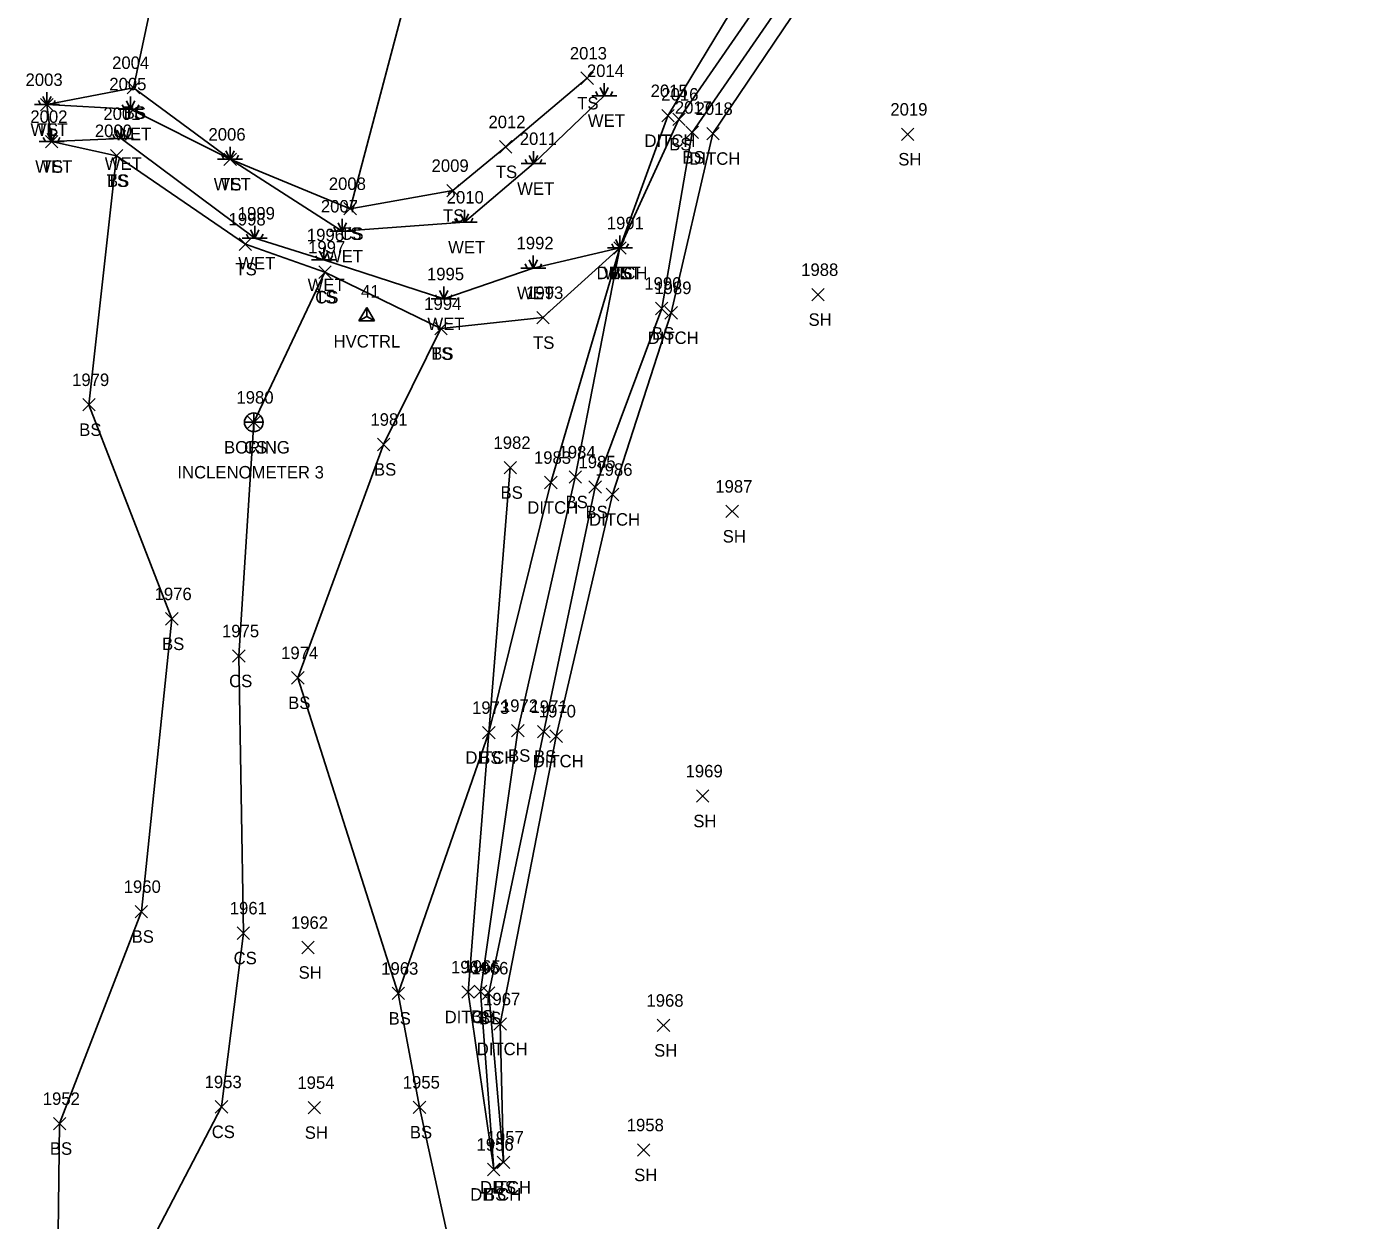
# Model space of a CAD drawing. Extents: x 1551995 to 1555700, y 777276 to 783130.
# Drawn here: x 1555046.7 to 1555258.3, y 777809.8 to 778001.3 of the extents above; entities that cross this region are included whole.
import ezdxf

# ---------------------------------------------------------------- set-up
doc = ezdxf.new("R2010")
doc.units = 0
for name, color, linetype in [('C_A', 7, 'Continuous'), ('C_I', 7, 'Continuous'), ('CPSM', 7, 'Continuous'), ('D_A', 7, 'Continuous'), ('D_I', 7, 'Continuous'), ('D_TIC', 7, 'Continuous'), ('DD', 7, 'Continuous'), ('G_A', 7, 'Continuous'), ('G_C', 7, 'Continuous'), ('G_I', 7, 'Continuous'), ('GA_P', 7, 'Continuous'), ('L_A', 7, 'Continuous'), ('L_I', 7, 'Continuous'), ('L_TIC', 7, 'Continuous'), ('LELB', 7, 'Continuous'), ('LWET', 7, 'Continuous')]:
    doc.layers.add(name, color=color, linetype=linetype)

msp = doc.modelspace()

# ---------------------------------------------------------------- linework, layer by layer
at = {"layer": 'CPSM'}
for p, q in [((1555100.02, 777954.05), (1555101.27, 777956.21)), ((1555102.52, 777954.05), (1555101.27, 777956.21)), ((1555101.27, 777954.77), (1555101.27, 777956.21)), ((1555100.02, 777954.05), (1555101.27, 777954.77)), ((1555100.02, 777954.05), (1555102.52, 777954.05)), ((1555101.27, 777954.77), (1555101.27, 777954.77)), ((1555101.27, 777954.77), (1555102.52, 777954.05))]:
    msp.add_line(p, q, dxfattribs=at)
at = {"layer": 'D_TIC'}
for points in [[(1555148.54, 777985.93), (1555150.54, 777987.93)], [(1555150.54, 777985.93), (1555148.54, 777987.93)], [(1555155.75, 777983.07), (1555157.75, 777985.07)], [(1555157.75, 777983.07), (1555155.75, 777985.07)], [(1555140.86, 777964.73), (1555142.86, 777966.73)], [(1555142.86, 777964.73), (1555140.86, 777966.73)], [(1555149.07, 777954.34), (1555151.07, 777956.34)], [(1555151.07, 777954.34), (1555149.07, 777956.34)], [(1555129.77, 777927.13), (1555131.77, 777929.13)], [(1555131.77, 777927.13), (1555129.77, 777929.13)], [(1555139.67, 777925.21), (1555141.67, 777927.21)], [(1555141.67, 777925.21), (1555139.67, 777927.21)], [(1555119.85, 777887.04), (1555121.85, 777889.04)], [(1555121.85, 777887.04), (1555119.85, 777889.04)], [(1555130.63, 777886.47), (1555132.63, 777888.47)], [(1555132.63, 777886.47), (1555130.63, 777888.47)], [(1555116.52, 777845.44), (1555118.52, 777847.44)], [(1555118.52, 777845.44), (1555116.52, 777847.44)], [(1555121.67, 777840.32), (1555123.67, 777842.32)], [(1555123.67, 777840.32), (1555121.67, 777842.32)], [(1555122.19, 777818.14), (1555124.19, 777820.14)], [(1555124.19, 777818.14), (1555122.19, 777820.14)], [(1555120.62, 777817), (1555122.62, 777819)], [(1555122.62, 777817), (1555120.62, 777819)], [(1555120.62, 777817), (1555122.62, 777819)], [(1555122.62, 777817), (1555120.62, 777819)]]:
    msp.add_lwpolyline(points, dxfattribs=at)
at = {"layer": 'DD'}
for points in [[(1555121.62, 777818), (1555123.19, 777819.14), (1555122.67, 777841.32), (1555131.63, 777887.47), (1555140.67, 777926.21), (1555150.07, 777955.34), (1555156.75, 777984.07), (1555186.15, 778027.75), (1555203.27, 778046.42), (1555232.38, 778067.51)], [(1555121.62, 777818), (1555117.52, 777846.44), (1555120.85, 777888.04), (1555130.77, 777928.13), (1555141.86, 777965.73), (1555149.54, 777986.93), (1555176.87, 778032.18)]]:
    msp.add_lwpolyline(points, dxfattribs=at)
at = {"layer": 'GA_P'}
for p, q in [((1555083.18, 777937.78), (1555083.18, 777939.28)), ((1555083.18, 777937.78), (1555081.68, 777937.78)), ((1555084.68, 777937.78), (1555083.18, 777937.78)), ((1555083.18, 777936.28), (1555083.18, 777937.78))]:
    msp.add_line(p, q, dxfattribs=at)
for start, end in [(90, 180), (0, 90), (180, 270), (270, 0)]:
    msp.add_arc((1555083.18, 777937.78), 1.5, start, end, dxfattribs=at)
at = {"layer": 'L_TIC'}
for points in [[(1555135.6, 777991.95), (1555137.6, 777993.95)], [(1555137.6, 777991.95), (1555135.6, 777993.95)], [(1555062.9, 777990.43), (1555064.9, 777992.43)], [(1555064.9, 777990.43), (1555062.9, 777992.43)], [(1555062.9, 777990.43), (1555064.9, 777992.43)], [(1555064.9, 777990.43), (1555062.9, 777992.43)], [(1555049.03, 777987.71), (1555051.03, 777989.71)], [(1555051.03, 777987.71), (1555049.03, 777989.71)], [(1555150.31, 777985.37), (1555152.31, 777987.37)], [(1555152.31, 777985.37), (1555150.31, 777987.37)], [(1555152.42, 777983.26), (1555154.42, 777985.26)], [(1555154.42, 777983.26), (1555152.42, 777985.26)], [(1555186.96, 777982.96), (1555188.96, 777984.96)], [(1555188.96, 777982.96), (1555186.96, 777984.96)], [(1555049.79, 777981.79), (1555051.79, 777983.79)], [(1555051.79, 777981.79), (1555049.79, 777983.79)], [(1555122.55, 777980.94), (1555124.55, 777982.94)], [(1555124.55, 777980.94), (1555122.55, 777982.94)], [(1555060.21, 777979.52), (1555062.21, 777981.52)], [(1555062.21, 777979.52), (1555060.21, 777981.52)], [(1555060.21, 777979.52), (1555062.21, 777981.52)], [(1555062.21, 777979.52), (1555060.21, 777981.52)], [(1555078.39, 777978.95), (1555080.39, 777980.95)], [(1555080.39, 777978.95), (1555078.39, 777980.95)], [(1555114.09, 777973.93), (1555116.09, 777975.93)], [(1555116.09, 777973.93), (1555114.09, 777975.93)], [(1555097.62, 777971.03), (1555099.62, 777973.03)], [(1555099.62, 777971.03), (1555097.62, 777973.03)], [(1555097.62, 777971.03), (1555099.62, 777973.03)], [(1555099.62, 777971.03), (1555097.62, 777973.03)], [(1555080.83, 777965.34), (1555082.83, 777967.34)], [(1555082.83, 777965.34), (1555080.83, 777967.34)], [(1555140.86, 777964.73), (1555142.86, 777966.73)], [(1555142.86, 777964.73), (1555140.86, 777966.73)], [(1555140.86, 777964.73), (1555142.86, 777966.73)], [(1555142.86, 777964.73), (1555140.86, 777966.73)], [(1555093.59, 777960.85), (1555095.59, 777962.85)], [(1555095.59, 777960.85), (1555093.59, 777962.85)], [(1555093.59, 777960.85), (1555095.59, 777962.85)], [(1555095.59, 777960.85), (1555093.59, 777962.85)], [(1555172.58, 777957.25), (1555174.58, 777959.25)], [(1555174.58, 777957.25), (1555172.58, 777959.25)], [(1555128.52, 777953.56), (1555130.52, 777955.56)], [(1555130.52, 777953.56), (1555128.52, 777955.56)], [(1555147.54, 777955.04), (1555149.54, 777957.04)], [(1555149.54, 777955.04), (1555147.54, 777957.04)], [(1555112.18, 777951.8), (1555114.18, 777953.8)], [(1555114.18, 777951.8), (1555112.18, 777953.8)], [(1555112.18, 777951.8), (1555114.18, 777953.8)], [(1555114.18, 777951.8), (1555112.18, 777953.8)], [(1555055.77, 777939.6), (1555057.77, 777941.6)], [(1555057.77, 777939.6), (1555055.77, 777941.6)], [(1555082.18, 777936.78), (1555084.18, 777938.78)], [(1555084.18, 777936.78), (1555082.18, 777938.78)], [(1555102.99, 777933.23), (1555104.99, 777935.23)], [(1555104.99, 777933.23), (1555102.99, 777935.23)], [(1555123.28, 777929.52), (1555125.28, 777931.52)], [(1555125.28, 777929.52), (1555123.28, 777931.52)], [(1555133.7, 777928), (1555135.7, 777930)], [(1555135.7, 777928), (1555133.7, 777930)], [(1555136.89, 777926.41), (1555138.89, 777928.41)], [(1555138.89, 777926.41), (1555136.89, 777928.41)], [(1555158.83, 777922.51), (1555160.83, 777924.51)], [(1555160.83, 777922.51), (1555158.83, 777924.51)], [(1555069.04, 777905.27), (1555071.04, 777907.27)], [(1555071.04, 777905.27), (1555069.04, 777907.27)], [(1555079.79, 777899.32), (1555081.79, 777901.32)], [(1555081.79, 777899.32), (1555079.79, 777901.32)], [(1555089.25, 777895.82), (1555091.25, 777897.82)], [(1555091.25, 777895.82), (1555089.25, 777897.82)], [(1555119.85, 777887.04), (1555121.85, 777889.04)], [(1555121.85, 777887.04), (1555119.85, 777889.04)], [(1555124.48, 777887.36), (1555126.48, 777889.36)], [(1555126.48, 777887.36), (1555124.48, 777889.36)], [(1555128.65, 777887.2), (1555130.65, 777889.2)], [(1555130.65, 777887.2), (1555128.65, 777889.2)], [(1555154.12, 777876.86), (1555156.12, 777878.86)], [(1555156.12, 777876.86), (1555154.12, 777878.86)], [(1555064.17, 777858.34), (1555066.17, 777860.34)], [(1555066.17, 777858.34), (1555064.17, 777860.34)], [(1555080.51, 777854.89), (1555082.51, 777856.89)], [(1555082.51, 777854.89), (1555080.51, 777856.89)], [(1555090.87, 777852.58), (1555092.87, 777854.58)], [(1555092.87, 777852.58), (1555090.87, 777854.58)], [(1555105.34, 777845.22), (1555107.34, 777847.22)], [(1555107.34, 777845.22), (1555105.34, 777847.22)], [(1555105.34, 777845.22), (1555107.34, 777847.22)], [(1555107.34, 777845.22), (1555105.34, 777847.22)], [(1555118.52, 777845.53), (1555120.52, 777847.53)], [(1555120.52, 777845.53), (1555118.52, 777847.53)], [(1555119.83, 777845.27), (1555121.83, 777847.27)], [(1555121.83, 777845.27), (1555119.83, 777847.27)], [(1555147.84, 777840.09), (1555149.84, 777842.09)], [(1555149.84, 777840.09), (1555147.84, 777842.09)], [(1555077, 777827.03), (1555079, 777829.03)], [(1555079, 777827.03), (1555077, 777829.03)], [(1555091.87, 777826.91), (1555093.87, 777828.91)], [(1555093.87, 777826.91), (1555091.87, 777828.91)], [(1555108.74, 777826.97), (1555110.74, 777828.97)], [(1555110.74, 777826.97), (1555108.74, 777828.97)], [(1555051.07, 777824.35), (1555053.07, 777826.35)], [(1555053.07, 777824.35), (1555051.07, 777826.35)], [(1555144.64, 777820.12), (1555146.64, 777822.12)], [(1555146.64, 777820.12), (1555144.64, 777822.12)], [(1555122.19, 777818.14), (1555124.19, 777820.14)], [(1555124.19, 777818.14), (1555122.19, 777820.14)], [(1555120.62, 777817), (1555122.62, 777819)], [(1555122.62, 777817), (1555120.62, 777819)]]:
    msp.add_lwpolyline(points, dxfattribs=at)
at = {"layer": 'LELB'}
for points in [[(1555121.62, 777818), (1555119.52, 777846.53), (1555125.48, 777888.36), (1555134.7, 777929), (1555141.86, 777965.73), (1555151.31, 777986.37), (1555183.22, 778032.67), (1555190.31, 778048.94), (1555214.6, 778082.43), (1555223.43, 778108.97), (1555230.38, 778127.63), (1555240.8, 778143.5)], [(1555123.19, 777819.14), (1555120.83, 777846.27), (1555129.65, 777888.2), (1555137.89, 777927.41), (1555148.54, 777956.04), (1555153.42, 777984.26), (1555185.28, 778030.41), (1555197.54, 778048.3), (1555227.98, 778071.92), (1555258.29, 778091.6)], [(1555063.9, 777991.43), (1555073.77, 778037.95)], [(1555098.62, 777972.03), (1555109.8, 778014.3)], [(1555050.03, 777988.71), (1555063.9, 777991.43), (1555079.39, 777979.95), (1555098.62, 777972.03), (1555115.09, 777974.93), (1555123.55, 777981.94), (1555136.6, 777992.95)], [(1555141.86, 777965.73), (1555129.52, 777954.56), (1555113.18, 777952.8), (1555094.59, 777961.85), (1555081.83, 777966.34), (1555061.21, 777980.52), (1555050.79, 777982.79)], [(1555058.64, 777737.23), (1555051.45, 777777.12), (1555052.07, 777825.35), (1555065.17, 777859.34), (1555070.04, 777906.27), (1555056.77, 777940.6), (1555061.21, 777980.52)], [(1555051.45, 777777.12), (1555078, 777828.03), (1555081.51, 777855.89), (1555080.79, 777900.32), (1555083.18, 777937.78), (1555094.59, 777961.85)], [(1555106.34, 777846.22), (1555090.25, 777896.82), (1555103.99, 777934.23), (1555113.18, 777952.8)], [(1555127.2, 777766.18), (1555120.97, 777776.63), (1555109.74, 777827.97), (1555106.34, 777846.22), (1555120.85, 777888.04), (1555124.28, 777930.52)]]:
    msp.add_lwpolyline(points, dxfattribs=at)
at = {"layer": 'LWET'}
for p, q in [((1555139.33, 777990.15), (1555138.66, 777991.48)), ((1555139.33, 777990.15), (1555139.33, 777992.15)), ((1555139.33, 777990.15), (1555139.99, 777991.48)), ((1555049.03, 777988.71), (1555048.7, 777989.38)), ((1555050.03, 777988.71), (1555049.36, 777990.04)), ((1555050.03, 777988.71), (1555050.03, 777990.71)), ((1555050.03, 777988.71), (1555050.7, 777990.04)), ((1555051.03, 777988.71), (1555051.36, 777989.38)), ((1555063.44, 777988.01), (1555062.78, 777989.34)), ((1555063.44, 777988.01), (1555063.44, 777990.01)), ((1555063.44, 777988.01), (1555064.11, 777989.34)), ((1555141.33, 777990.15), (1555137.33, 777990.15)), ((1555138.33, 777990.15), (1555137.99, 777990.82)), ((1555140.33, 777990.15), (1555140.66, 777990.82)), ((1555052.03, 777988.71), (1555048.03, 777988.71)), ((1555065.44, 777988.01), (1555061.44, 777988.01)), ((1555062.44, 777988.01), (1555062.11, 777988.68)), ((1555064.44, 777988.01), (1555064.78, 777988.68)), ((1555050.79, 777982.79), (1555050.79, 777984.79)), ((1555061.93, 777983.26), (1555061.93, 777985.26)), ((1555052.79, 777982.79), (1555048.79, 777982.79)), ((1555049.79, 777982.79), (1555049.46, 777983.46)), ((1555050.79, 777982.79), (1555050.13, 777984.12)), ((1555050.79, 777982.79), (1555051.46, 777984.12)), ((1555051.79, 777982.79), (1555052.13, 777983.46)), ((1555063.93, 777983.26), (1555059.93, 777983.26)), ((1555060.93, 777983.26), (1555060.6, 777983.93)), ((1555061.93, 777983.26), (1555061.27, 777984.6)), ((1555061.93, 777983.26), (1555062.6, 777984.6)), ((1555062.93, 777983.26), (1555063.27, 777983.93)), ((1555078.39, 777979.95), (1555078.06, 777980.62)), ((1555079.39, 777979.95), (1555078.72, 777981.29)), ((1555079.39, 777979.95), (1555079.39, 777981.95)), ((1555079.39, 777979.95), (1555080.06, 777981.29)), ((1555080.39, 777979.95), (1555080.72, 777980.62)), ((1555128, 777979.25), (1555127.33, 777980.58)), ((1555128, 777979.25), (1555128, 777981.25)), ((1555128, 777979.25), (1555128.67, 777980.58)), ((1555081.39, 777979.95), (1555077.39, 777979.95)), ((1555130, 777979.25), (1555126, 777979.25)), ((1555127, 777979.25), (1555126.67, 777979.92)), ((1555129, 777979.25), (1555129.33, 777979.92)), ((1555097.35, 777968.42), (1555097.35, 777970.42)), ((1555118.95, 777969.86), (1555114.95, 777969.86)), ((1555115.95, 777969.86), (1555115.61, 777970.52)), ((1555116.95, 777969.86), (1555116.28, 777971.19)), ((1555116.95, 777969.86), (1555116.95, 777971.86)), ((1555116.95, 777969.86), (1555117.61, 777971.19)), ((1555117.95, 777969.86), (1555118.28, 777970.52)), ((1555082.33, 777967.3), (1555081.99, 777967.97)), ((1555083.33, 777967.3), (1555082.66, 777968.64)), ((1555083.33, 777967.3), (1555083.33, 777969.3)), ((1555083.33, 777967.3), (1555083.99, 777968.64)), ((1555084.33, 777967.3), (1555084.66, 777967.97)), ((1555099.35, 777968.42), (1555095.35, 777968.42)), ((1555096.35, 777968.42), (1555096.02, 777969.09)), ((1555097.35, 777968.42), (1555096.69, 777969.75)), ((1555097.35, 777968.42), (1555098.02, 777969.75)), ((1555098.35, 777968.42), (1555098.69, 777969.09)), ((1555141.86, 777965.73), (1555141.86, 777967.73)), ((1555085.33, 777967.3), (1555081.33, 777967.3)), ((1555094.43, 777963.82), (1555094.43, 777965.82)), ((1555143.86, 777965.73), (1555139.86, 777965.73)), ((1555140.86, 777965.73), (1555140.53, 777966.4)), ((1555141.86, 777965.73), (1555141.2, 777967.07)), ((1555141.86, 777965.73), (1555142.53, 777967.07)), ((1555142.86, 777965.73), (1555143.2, 777966.4)), ((1555096.43, 777963.82), (1555092.43, 777963.82)), ((1555093.43, 777963.82), (1555093.1, 777964.48)), ((1555094.43, 777963.82), (1555093.77, 777965.15)), ((1555094.43, 777963.82), (1555095.1, 777965.15)), ((1555095.43, 777963.82), (1555095.77, 777964.48)), ((1555127.97, 777962.52), (1555127.31, 777963.85)), ((1555127.97, 777962.52), (1555127.97, 777964.52)), ((1555127.97, 777962.52), (1555128.64, 777963.85)), ((1555129.97, 777962.52), (1555125.97, 777962.52)), ((1555126.97, 777962.52), (1555126.64, 777963.19)), ((1555128.97, 777962.52), (1555129.31, 777963.19)), ((1555113.62, 777957.56), (1555113.62, 777959.56)), ((1555115.62, 777957.56), (1555111.62, 777957.56)), ((1555112.62, 777957.56), (1555112.29, 777958.23)), ((1555113.62, 777957.56), (1555112.95, 777958.89)), ((1555113.62, 777957.56), (1555114.29, 777958.89)), ((1555114.62, 777957.56), (1555114.95, 777958.23))]:
    msp.add_line(p, q, dxfattribs=at)
msp.add_lwpolyline([(1555141.86, 777965.73), (1555127.97, 777962.52), (1555113.62, 777957.56), (1555094.43, 777963.82), (1555083.33, 777967.3), (1555061.93, 777983.26), (1555050.79, 777982.79), (1555050.03, 777988.71), (1555063.44, 777988.01), (1555079.39, 777979.95), (1555097.35, 777968.42), (1555116.95, 777969.86), (1555128, 777979.25), (1555139.33, 777990.15)], dxfattribs=at)

# ---------------------------------------------------------------- texts
at = {"layer": 'C_A'}
msp.add_text('HVCTRL', height=2, dxfattribs=at).set_placement((1555095.96, 777949.77))
at = {"layer": 'C_I'}
msp.add_text('41', height=2, dxfattribs=at).set_placement((1555100.37, 777957.77))
at = {"layer": 'D_A'}
for p in [(1555145.78, 777981.93), (1555152.98, 777979.07), (1555138.1, 777960.73), (1555146.3, 777950.34), (1555127, 777923.13), (1555136.91, 777921.21), (1555117.09, 777883.04), (1555127.87, 777882.47), (1555113.76, 777841.44), (1555118.9, 777836.32), (1555119.43, 777814.14), (1555117.86, 777813), (1555117.86, 777813)]:
    msp.add_text('DITCH', height=2, dxfattribs=at).set_placement(p)
at = {"layer": 'D_I'}
for s, p in [('2015', (1555146.77, 777989.93)), ('2018', (1555153.98, 777987.07)), ('1991', (1555139.74, 777968.73)), ('1989', (1555147.37, 777958.34)), ('1983', (1555128.07, 777931.13)), ('1986', (1555137.92, 777929.21)), ('1973', (1555118.16, 777891.04)), ('1970', (1555128.85, 777890.47)), ('1964', (1555114.78, 777849.44)), ('1967', (1555119.93, 777844.32)), ('1957', (1555120.5, 777822.14)), ('1956', (1555118.87, 777821)), ('1956', (1555118.87, 777821))]:
    msp.add_text(s, height=2, dxfattribs=at).set_placement(p)
at = {"layer": 'G_A'}
msp.add_text('BORING', height=2, dxfattribs=at).set_placement((1555078.41, 777932.78))
at = {"layer": 'G_C'}
msp.add_text('INCLENOMETER 3', height=2, dxfattribs=at).set_placement((1555070.94, 777928.78))
at = {"layer": 'G_I'}
msp.add_text('1980', height=2, dxfattribs=at).set_placement((1555080.4, 777940.78))
at = {"layer": 'L_A'}
for s, p in [('TS', (1555135.01, 777987.95)), ('TS', (1555062.31, 777986.43)), ('BS', (1555062.34, 777986.43)), ('WET', (1555136.71, 777985.15)), ('WET', (1555047.41, 777983.71)), ('TS', (1555048.44, 777983.71)), ('WET', (1555060.82, 777983.01)), ('BS', (1555149.75, 777981.37)), ('BS', (1555151.87, 777979.26)), ('SH', (1555186.45, 777978.96)), ('WET', (1555048.17, 777977.79)), ('TS', (1555049.2, 777977.79)), ('WET', (1555059.31, 777978.26)), ('TS', (1555121.96, 777976.94)), ('TS', (1555059.62, 777975.52)), ('BS', (1555059.65, 777975.52)), ('WET', (1555076.77, 777974.95)), ('TS', (1555077.8, 777974.95)), ('WET', (1555125.38, 777974.25)), ('TS', (1555113.5, 777969.93)), ('TS', (1555097.03, 777967.03)), ('CS', (1555097.06, 777967.03)), ('WET', (1555114.32, 777964.86)), ('WET', (1555080.7, 777962.3)), ('WET', (1555094.73, 777963.42)), ('TS', (1555080.24, 777961.34)), ('WET', (1555139.24, 777960.73)), ('TS', (1555140.27, 777960.73)), ('BS', (1555140.3, 777960.73)), ('WET', (1555091.81, 777958.82)), ('WET', (1555125.35, 777957.52)), ('TS', (1555093, 777956.85)), ('CS', (1555093.03, 777956.85)), ('SH', (1555172.07, 777953.25)), ('WET', (1555111, 777952.56)), ('BS', (1555146.98, 777951.04)), ('TS', (1555127.93, 777949.56)), ('TS', (1555111.59, 777947.8)), ('BS', (1555111.62, 777947.8)), ('BS', (1555055.21, 777935.6)), ('CS', (1555081.62, 777932.78)), ('BS', (1555102.44, 777929.23)), ('BS', (1555122.72, 777925.52)), ('BS', (1555133.14, 777924)), ('BS', (1555136.33, 777922.41)), ('SH', (1555158.32, 777918.51)), ('BS', (1555068.48, 777901.27)), ('CS', (1555079.23, 777895.32)), ('BS', (1555088.69, 777891.82)), ('BS', (1555123.92, 777883.36)), ('BS', (1555128.09, 777883.2)), ('BS', (1555119.29, 777883.04)), ('SH', (1555153.61, 777872.86)), ('BS', (1555063.61, 777854.34)), ('CS', (1555079.95, 777850.89)), ('SH', (1555090.36, 777848.58)), ('BS', (1555104.78, 777841.22)), ('BS', (1555104.78, 777841.22)), ('BS', (1555117.96, 777841.53)), ('BS', (1555119.27, 777841.27)), ('SH', (1555147.33, 777836.09)), ('CS', (1555076.44, 777823.03)), ('SH', (1555091.35, 777822.91)), ('BS', (1555108.19, 777822.97)), ('BS', (1555050.51, 777820.35)), ('SH', (1555144.13, 777816.12)), ('BS', (1555121.63, 777814.14)), ('BS', (1555120.06, 777813))]:
    msp.add_text(s, height=2, dxfattribs=at).set_placement(p)
at = {"layer": 'L_I'}
for s, p in [('2013', (1555133.82, 777995.95)), ('2004', (1555060.48, 777994.43)), ('2004', (1555060.48, 777994.43)), ('2003', (1555046.61, 777991.71)), ('2003', (1555046.61, 777991.71)), ('2014', (1555136.56, 777993.15)), ('2005', (1555060.03, 777991.01)), ('2016', (1555148.48, 777989.37)), ('2017', (1555150.65, 777987.26)), ('2019', (1555185.18, 777986.96)), ('2002', (1555047.38, 777985.79)), ('2002', (1555047.38, 777985.79)), ('2001', (1555059.08, 777986.26)), ('2012', (1555120.78, 777984.94)), ('2000', (1555057.71, 777983.52)), ('2000', (1555057.71, 777983.52)), ('2006', (1555075.92, 777982.95)), ('2006', (1555075.92, 777982.95)), ('2011', (1555125.8, 777982.25)), ('2009', (1555111.67, 777977.93)), ('2008', (1555095.2, 777975.03)), ('2008', (1555095.2, 777975.03)), ('2010', (1555114.09, 777972.86)), ('1999', (1555080.62, 777970.3)), ('2007', (1555093.93, 777971.42)), ('1998', (1555079.14, 777969.34)), ('1991', (1555139.74, 777968.73)), ('1991', (1555139.74, 777968.73)), ('1991', (1555139.74, 777968.73)), ('1996', (1555091.69, 777966.82)), ('1997', (1555091.89, 777964.85)), ('1997', (1555091.89, 777964.85)), ('1992', (1555125.28, 777965.52)), ('1995', (1555110.93, 777960.56)), ('1988', (1555170.89, 777961.25)), ('1993', (1555126.83, 777957.56)), ('1990', (1555145.76, 777959.04)), ('1994', (1555110.49, 777955.8)), ('1994', (1555110.49, 777955.8)), ('1979', (1555054.07, 777943.6)), ('1980', (1555080.4, 777940.78)), ('1981', (1555101.87, 777937.23)), ('1982', (1555121.59, 777933.52)), ('1984', (1555132.01, 777932)), ('1985', (1555135.2, 777930.41)), ('1987', (1555157.13, 777926.51)), ('1976', (1555067.29, 777909.27)), ('1975', (1555078.09, 777903.32)), ('1974', (1555087.56, 777899.82)), ('1973', (1555118.16, 777891.04)), ('1972', (1555122.78, 777891.36)), ('1971', (1555127.52, 777891.2)), ('1969', (1555152.37, 777880.86)), ('1960', (1555062.34, 777862.34)), ('1961', (1555079.33, 777858.89)), ('1962', (1555089.13, 777856.58)), ('1965', (1555116.78, 777849.53)), ('1963', (1555103.6, 777849.22)), ('1963', (1555103.6, 777849.22)), ('1966', (1555118.03, 777849.27)), ('1968', (1555146.1, 777844.09)), ('1953', (1555075.3, 777831.03)), ('1954', (1555090.17, 777830.91)), ('1955', (1555107.05, 777830.97)), ('1952', (1555049.37, 777828.35)), ('1958', (1555142.94, 777824.12)), ('1957', (1555120.5, 777822.14)), ('1956', (1555118.87, 777821))]:
    msp.add_text(s, height=2, dxfattribs=at).set_placement(p)

doc.saveas('drawing.dxf')
